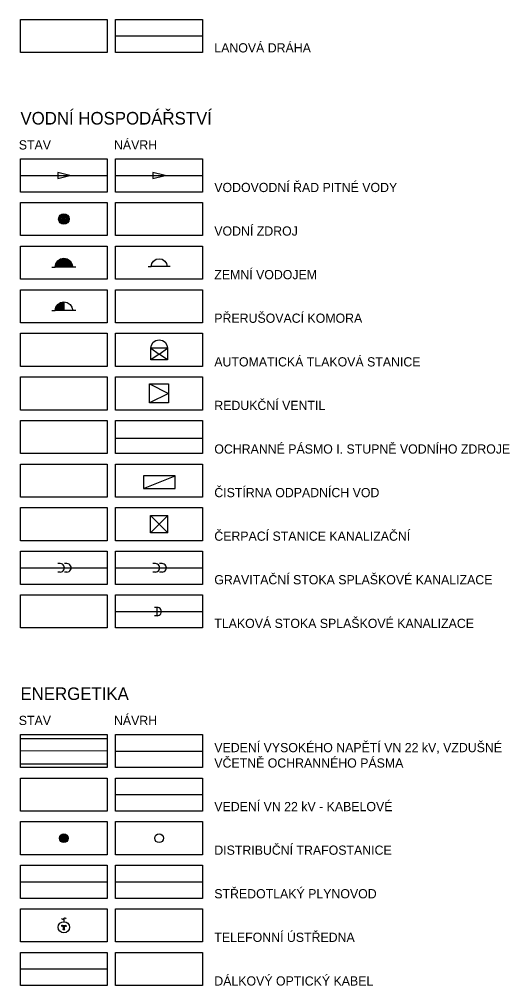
# Model space of a CAD drawing. Extents: x -439236 to -436121, y -1128919 to -1121098.
# Drawn here: x -439126 to -438541, y -1128630 to -1127477 of the extents above; entities that cross this region are included whole.
import ezdxf

# ---------------------------------------------------------------- set-up
doc = ezdxf.new("R2010")
doc.units = 0
for name, color, linetype in [('12210022_lanová dráha_Návrh', 7, 'Continuous'), ('13861012_venkovní vedení elektrické sítě VN 1-35 kV_Stav', 7, 'Continuous'), ('14250012_plynovod STL_Stav', 7, 'Continuous'), ('14801013_OP vedení elektrické sítě_Stav', 7, 'Continuous'), ('Trafostanice', 7, 'Continuous'), ('Vrstva 1', 7, 'Continuous'), ('Vrstva 10', 7, 'Continuous'), ('Vrstva 11', 7, 'Continuous'), ('Vrstva 12', 7, 'Continuous'), ('Vrstva 13', 7, 'Continuous'), ('Vrstva 14', 7, 'Continuous'), ('Vrstva 19', 7, 'Continuous'), ('Vrstva 27', 7, 'Continuous'), ('Vrstva 33', 7, 'Continuous'), ('Vrstva 34', 7, 'Continuous'), ('Vrstva 36', 7, 'Continuous'), ('Vrstva 39', 7, 'Continuous'), ('Vrstva 57', 7, 'Continuous'), ('Vrstva 58', 7, 'Continuous'), ('Vrstva 9', 7, 'Continuous')]:
    doc.layers.add(name, color=color, linetype=linetype)

msp = doc.modelspace()

# ---------------------------------------------------------------- linework, layer by layer
at = {"layer": '12210022_lanová dráha_Návrh'}
msp.add_line((-439011.8, -1127496.6), (-438907.2, -1127496.6), dxfattribs=at)
at = {"layer": '13861012_venkovní vedení elektrické sítě VN 1-35 kV_Stav'}
msp.add_line((-439011.3, -1128350), (-438907.7, -1128350), dxfattribs=at)
msp.add_lwpolyline([(-439021.3, -1128349.9), (-439124.9, -1128350.1)], dxfattribs=at)
at = {"layer": '14250012_plynovod STL_Stav'}
for p, q in [((-439124.9, -1128506.1), (-439021.3, -1128506.1)), ((-439011.3, -1128506.1), (-438907.7, -1128506.1))]:
    msp.add_line(p, q, dxfattribs=at)
at = {"layer": '14801013_OP vedení elektrické sítě_Stav'}
for p, q in [((-439124.9, -1128334.9), (-439021.3, -1128334.9)), ((-439021.3, -1128365.5), (-439124.9, -1128365.5))]:
    msp.add_line(p, q, dxfattribs=at)
at = {"layer": 'Trafostanice'}
for radius in [5.25, 4.55, 3.85, 3.15, 2.45, 1.75, 1.05, 0.35]:
    msp.add_circle((-439073.1, -1128454.1), radius, dxfattribs=at)
at = {"layer": 'Vrstva 1'}
for points in [[(-439124.9, -1127476.9), (-439021.3, -1127476.9), (-439021.3, -1127476.9), (-439021.3, -1127516.4), (-439124.9, -1127516.4)], [(-439011.3, -1127476.9), (-438907.7, -1127476.9), (-438907.7, -1127516.4), (-439011.3, -1127516.4)], [(-439124.9, -1127643.5), (-439021.3, -1127643.5), (-439021.3, -1127643.5), (-439021.3, -1127683), (-439124.9, -1127683)], [(-439011.3, -1127643.5), (-438907.7, -1127643.5), (-438907.7, -1127643.5), (-438907.7, -1127683), (-439011.3, -1127683)], [(-439124.9, -1127695.5), (-439021.3, -1127695.5), (-439021.3, -1127695.5), (-439021.3, -1127735), (-439124.9, -1127735)], [(-439011.3, -1127695.5), (-438907.7, -1127695.5), (-438907.7, -1127735), (-439011.3, -1127735)], [(-439124.9, -1127747.5), (-439021.3, -1127747.5), (-439021.3, -1127747.5), (-439021.3, -1127787), (-439124.9, -1127787)], [(-439011.3, -1127747.5), (-438907.7, -1127747.5), (-438907.7, -1127787), (-439011.3, -1127787)], [(-439124.9, -1127799.5), (-439021.3, -1127799.5), (-439021.3, -1127799.5), (-439021.3, -1127839), (-439124.9, -1127839)], [(-439011.3, -1127799.5), (-438907.7, -1127799.5), (-438907.7, -1127839), (-439011.3, -1127839)], [(-439124.9, -1127851.5), (-439021.3, -1127851.5), (-439021.3, -1127851.5), (-439021.3, -1127891.1), (-439124.9, -1127891.1)], [(-439011.3, -1127851.5), (-438907.7, -1127851.5), (-438907.7, -1127891.1), (-439011.3, -1127891.1)], [(-439124.9, -1127903.6), (-439021.3, -1127903.6), (-439021.3, -1127903.6), (-439021.3, -1127943.1), (-439124.9, -1127943.1)], [(-439011.3, -1127903.6), (-438907.7, -1127903.6), (-438907.7, -1127943.1), (-439011.3, -1127943.1)], [(-439124.9, -1127955.6), (-439021.3, -1127955.6), (-439021.3, -1127955.6), (-439021.3, -1127995.1), (-439124.9, -1127995.1)], [(-439011.3, -1127955.6), (-438907.7, -1127955.6), (-438907.7, -1127995.1), (-439011.3, -1127995.1)], [(-439124.9, -1128007.6), (-439021.3, -1128007.6), (-439021.3, -1128007.6), (-439021.3, -1128047.1), (-439124.9, -1128047.1)], [(-439011.3, -1128007.6), (-438907.7, -1128007.6), (-438907.7, -1128047.1), (-439011.3, -1128047.1)], [(-439124.9, -1128059.6), (-439021.3, -1128059.6), (-439021.3, -1128059.6), (-439021.3, -1128099.1), (-439124.9, -1128099.1)], [(-439011.3, -1128059.6), (-438907.7, -1128059.6), (-438907.7, -1128099.1), (-439011.3, -1128099.1)], [(-439124.9, -1128111.6), (-439021.3, -1128111.6), (-439021.3, -1128111.6), (-439021.3, -1128151.1), (-439124.9, -1128151.1)], [(-439011.3, -1128111.6), (-438907.7, -1128111.6), (-438907.7, -1128151.1), (-439011.3, -1128151.1)], [(-439124.9, -1128163.7), (-439021.3, -1128163.7), (-439021.3, -1128163.7), (-439021.3, -1128203.2), (-439124.9, -1128203.2)], [(-439011.3, -1128163.7), (-438907.7, -1128163.7), (-438907.7, -1128203.2), (-439011.3, -1128203.2)], [(-439124.9, -1128330.3), (-439021.3, -1128330.3), (-439021.3, -1128330.3), (-439021.3, -1128369.8), (-439124.9, -1128369.8)], [(-439011.3, -1128330.3), (-438907.7, -1128330.3), (-438907.7, -1128330.3), (-438907.7, -1128369.8), (-439011.3, -1128369.8)], [(-439124.9, -1128382.3), (-439021.3, -1128382.3), (-439021.3, -1128382.3), (-439021.3, -1128421.8), (-439124.9, -1128421.8)], [(-439011.3, -1128382.3), (-438907.7, -1128382.3), (-438907.7, -1128421.8), (-439011.3, -1128421.8)], [(-439124.9, -1128434.3), (-439021.3, -1128434.3), (-439021.3, -1128434.3), (-439021.3, -1128473.8), (-439124.9, -1128473.8)], [(-439011.3, -1128434.3), (-438907.7, -1128434.3), (-438907.7, -1128473.8), (-439011.3, -1128473.8)], [(-439124.9, -1128486.3), (-439021.3, -1128486.3), (-439021.3, -1128486.3), (-439021.3, -1128525.8), (-439124.9, -1128525.8)], [(-439011.3, -1128486.3), (-438907.7, -1128486.3), (-438907.7, -1128525.8), (-439011.3, -1128525.8)], [(-439124.9, -1128538.3), (-439021.3, -1128538.3), (-439021.3, -1128538.3), (-439021.3, -1128577.8), (-439124.9, -1128577.8)], [(-439011.3, -1128538.3), (-438907.7, -1128538.3), (-438907.7, -1128577.8), (-439011.3, -1128577.8)], [(-439124.9, -1128590.4), (-439021.3, -1128590.4), (-439021.3, -1128590.4), (-439021.3, -1128629.9), (-439124.9, -1128629.9)], [(-439011.3, -1128590.4), (-438907.7, -1128590.4), (-438907.7, -1128629.9), (-439011.3, -1128629.9)]]:
    msp.add_lwpolyline(points, close=True, dxfattribs=at)
at = {"layer": 'Vrstva 10'}
for p, q in [((-438972.6, -1127772), (-438969, -1127772)), ((-438946.3, -1127772), (-438949.9, -1127772)), ((-438949.5, -1127883.3), (-438969.5, -1127883.3))]:
    msp.add_line(p, q, dxfattribs=at)
for points in [[(-438969, -1127772), (-438968.3, -1127768.4), (-438966.2, -1127765.3), (-438963.1, -1127763.2), (-438959.5, -1127762.5), (-438955.8, -1127763.2), (-438952.7, -1127765.3), (-438950.7, -1127768.4), (-438949.9, -1127772)], [(-438969.5, -1127869.3), (-438968.7, -1127865.5), (-438966.5, -1127862.2), (-438963.3, -1127860.1), (-438959.5, -1127859.3), (-438955.6, -1127860.1), (-438952.4, -1127862.2), (-438950.2, -1127865.5), (-438949.5, -1127869.3)], [(-438969.5, -1127869.3), (-438959.5, -1127876.3), (-438969.5, -1127883.3)], [(-438949.5, -1127869.3), (-438949.5, -1127883.3), (-438959.5, -1127876.3)], [(-438970.8, -1127912), (-438948.2, -1127923.3), (-438970.8, -1127934.6)]]:
    msp.add_lwpolyline(points, close=True, dxfattribs=at)
msp.add_lwpolyline([(-438970.8, -1127912), (-438948.2, -1127912), (-438948.2, -1127923.3), (-438948.2, -1127934.6), (-438970.8, -1127934.6)], dxfattribs=at)
at = {"layer": 'Vrstva 11'}
for p, q in [((-439124.9, -1127663.2), (-439021.3, -1127663.2)), ((-439087.5, -1127824.5), (-439083.5, -1127824.5)), ((-439058.7, -1127824.5), (-439062.6, -1127824.5))]:
    msp.add_line(p, q, dxfattribs=at)
for points in [[(-439083.5, -1127824.5), (-439082.7, -1127820.5), (-439080.5, -1127817.1), (-439077.1, -1127814.9), (-439073.1, -1127814.1), (-439073.1, -1127824.5)], [(-439082.3, -1127823.5), (-439081.8, -1127820.9), (-439079.8, -1127817.8), (-439076.7, -1127815.8), (-439074.1, -1127815.3), (-439074.1, -1127823.5)], [(-439081.1, -1127822.5), (-439080.9, -1127821.3), (-439079, -1127818.6), (-439076.3, -1127816.7), (-439075.1, -1127816.5), (-439075.1, -1127822.5)], [(-439078.3, -1127819.3), (-439076.1, -1127817.8), (-439076.1, -1127821.5), (-439079.8, -1127821.5)], [(-439077.9, -1127820.5), (-439077.6, -1127820), (-439077.1, -1127819.7), (-439077.1, -1127820.5)]]:
    msp.add_lwpolyline(points, close=True, dxfattribs=at)
msp.add_lwpolyline([(-439073.1, -1127814.1), (-439069.1, -1127814.9), (-439065.7, -1127817.1), (-439063.4, -1127820.5), (-439062.6, -1127824.5), (-439073.1, -1127824.5)], dxfattribs=at)
at = {"layer": 'Vrstva 12'}
msp.add_lwpolyline([(-439080.4, -1127659.6), (-439080.4, -1127666.9), (-439065.8, -1127663.2)], close=True, dxfattribs=at)
at = {"layer": 'Vrstva 13'}
for p, q in [((-439011.3, -1127663.3), (-438907.7, -1127663.1)), ((-439011.3, -1128402), (-438907.7, -1128402))]:
    msp.add_line(p, q, dxfattribs=at)
at = {"layer": 'Vrstva 14'}
msp.add_lwpolyline([(-438966.8, -1127659.6), (-438966.8, -1127666.9), (-438952.2, -1127663.2)], close=True, dxfattribs=at)
at = {"layer": 'Vrstva 19'}
msp.add_circle((-438959.5, -1128454.1), 5.25, dxfattribs=at)
at = {"layer": 'Vrstva 27'}
msp.add_line((-439011.3, -1127976.7), (-438907.7, -1127976.7), dxfattribs=at)
at = {"layer": 'Vrstva 33'}
for p, q in [((-438969.7, -1128069.1), (-438949.2, -1128069.1)), ((-438969.7, -1128069.1), (-438949.2, -1128089.7)), ((-438969.7, -1128089.7), (-438969.7, -1128069.1)), ((-438949.2, -1128069.1), (-438959.5, -1128079.4)), ((-438949.2, -1128089.7), (-438949.2, -1128069.1)), ((-438959.5, -1128079.4), (-438969.7, -1128089.7)), ((-438949.2, -1128089.7), (-438969.7, -1128089.7))]:
    msp.add_line(p, q, dxfattribs=at)
msp.add_lwpolyline([(-438978.1, -1128036.7), (-438940.3, -1128036.7), (-438940.3, -1128021.5), (-438978.1, -1128021.5)], close=True, dxfattribs=at)
msp.add_lwpolyline([(-438978.1, -1128036.7), (-438940.3, -1128021.5)], dxfattribs=at)
at = {"layer": 'Vrstva 34'}
msp.add_line((-439124.9, -1128131.4), (-439021.3, -1128131.4), dxfattribs=at)
at = {"layer": 'Vrstva 36'}
for p, q in [((-439011.3, -1128131.4), (-438907.7, -1128131.4)), ((-439011.3, -1128183.4), (-438907.7, -1128183.4))]:
    msp.add_line(p, q, dxfattribs=at)
at = {"layer": 'Vrstva 39'}
for p, q in [((-439077.4, -1128126.4), (-439080.4, -1128126.4)), ((-439069.4, -1128126.4), (-439072.4, -1128126.4)), ((-438963.8, -1128126.4), (-438966.8, -1128126.4)), ((-438955.8, -1128126.4), (-438958.8, -1128126.4)), ((-439077.4, -1128136.4), (-439080.4, -1128136.4)), ((-439069.4, -1128136.4), (-439072.4, -1128136.4)), ((-438963.8, -1128136.4), (-438966.8, -1128136.4)), ((-438955.8, -1128136.4), (-438958.8, -1128136.4)), ((-438961.9, -1128178.6), (-438964.9, -1128178.6)), ((-438961.9, -1128188.6), (-438961.9, -1128178.6)), ((-438961.9, -1128188.6), (-438964.9, -1128188.6))]:
    msp.add_line(p, q, dxfattribs=at)
for centre, start in [((-439077.4, -1128131.4), 270), ((-439069.4, -1128131.4), 270), ((-438963.8, -1128131.4), 270), ((-438955.8, -1128131.4), 270), ((-438961.9, -1128183.6), 270.0004)]:
    msp.add_arc(centre, 5, start, 90.0011, dxfattribs=at)
at = {"layer": 'Vrstva 57'}
for p, q in [((-439073.1, -1128549.9), (-439073.1, -1128553.6)), ((-439075.2, -1128559.2), (-439075.5, -1128558.9)), ((-439074.8, -1128558.8), (-439075.4, -1128558.2)), ((-439074.5, -1128558.5), (-439074.8, -1128558.1)), ((-439073.8, -1128558.5), (-439074.1, -1128558.1)), ((-439073.8, -1128563.4), (-439074, -1128563.1)), ((-439073.1, -1128563.4), (-439073.7, -1128562.8)), ((-439072.6, -1128558.9), (-439073.4, -1128558.1)), ((-439072.6, -1128559.6), (-439073.4, -1128558.9)), ((-439072.6, -1128560.3), (-439073.4, -1128559.6)), ((-439072.6, -1128561), (-439073.4, -1128560.3)), ((-439072.6, -1128561.7), (-439073.4, -1128561)), ((-439072.6, -1128562.4), (-439073.4, -1128561.7)), ((-439072.4, -1128563.4), (-439073.4, -1128562.4)), ((-439072.4, -1128558.5), (-439072.7, -1128558.1)), ((-439071.6, -1128558.5), (-439072, -1128558.1)), ((-439070.5, -1128558.9), (-439071.3, -1128558.1)), ((-439070.6, -1128558.1), (-439070.7, -1128558))]:
    msp.add_line(p, q, dxfattribs=at)
msp.add_lwpolyline([(-439076, -1128549.4), (-439075.5, -1128550.1), (-439074.8, -1128550.6), (-439074.4, -1128550.7), (-439074, -1128550.6), (-439073.5, -1128550.3), (-439073.1, -1128549.9), (-439072.7, -1128549.4), (-439072.1, -1128549.1), (-439071.7, -1128549.1), (-439071.3, -1128549.2), (-439070.7, -1128549.7), (-439070.2, -1128550.3)], dxfattribs=at)
msp.add_lwpolyline([(-439070.6, -1128558), (-439070.4, -1128559.4), (-439070.6, -1128559.4), (-439071.5, -1128558.5), (-439072.6, -1128558.5), (-439072.6, -1128562.6), (-439071.9, -1128563.2), (-439071.9, -1128563.4), (-439074.1, -1128563.4), (-439074.1, -1128563.2), (-439073.4, -1128562.6), (-439073.4, -1128558.5), (-439074.5, -1128558.5), (-439075.4, -1128559.4), (-439075.6, -1128559.4), (-439075.4, -1128558), (-439075.2, -1128558), (-439074.9, -1128558.1), (-439071.1, -1128558.1), (-439070.8, -1128558)], close=True, dxfattribs=at)
msp.add_circle((-439073.1, -1128560.4), 6.75, dxfattribs=at)
at = {"layer": 'Vrstva 58'}
msp.add_line((-439124.9, -1128610.1), (-439021.3, -1128610.1), dxfattribs=at)
at = {"layer": 'Vrstva 9'}
for p, q in [((-439087.5, -1127772.5), (-439083.5, -1127772.5)), ((-439058.7, -1127772.5), (-439062.6, -1127772.5))]:
    msp.add_line(p, q, dxfattribs=at)
for points in [[(-439083.5, -1127772.5), (-439082.7, -1127768.5), (-439080.5, -1127765.1), (-439077.1, -1127762.8), (-439073.1, -1127762), (-439069.1, -1127762.8), (-439065.7, -1127765.1), (-439063.4, -1127768.5), (-439062.6, -1127772.5)], [(-439082.3, -1127771.5), (-439081.8, -1127768.9), (-439079.8, -1127765.8), (-439076.7, -1127763.8), (-439073.1, -1127763.1), (-439069.5, -1127763.8), (-439066.4, -1127765.8), (-439064.4, -1127768.9), (-439063.9, -1127771.5)], [(-439081.1, -1127770.5), (-439080.9, -1127769.3), (-439079, -1127766.5), (-439076.3, -1127764.7), (-439073.1, -1127764.1), (-439069.9, -1127764.7), (-439067.1, -1127766.5), (-439065.3, -1127769.3), (-439065.1, -1127770.5)], [(-439079.8, -1127769.5), (-439078.3, -1127767.3), (-439075.9, -1127765.7), (-439073.1, -1127765.1), (-439070.3, -1127765.7), (-439067.9, -1127767.3), (-439066.4, -1127769.5)], [(-439077.9, -1127768.5), (-439077.6, -1127768), (-439075.5, -1127766.6), (-439073.1, -1127766.1), (-439070.6, -1127766.6), (-439068.6, -1127768), (-439068.2, -1127768.5)], [(-439074.9, -1127767.5), (-439073.1, -1127767.1), (-439071.3, -1127767.5)]]:
    msp.add_lwpolyline(points, close=True, dxfattribs=at)
for radius in [6.3, 5.3, 4.3, 3.3, 2.3, 1.3, 0.3]:
    msp.add_circle((-439073.1, -1127715.2), radius, dxfattribs=at)

# ---------------------------------------------------------------- texts
at = {"layer": 'Vrstva 1'}
for s, height, p in [('LANOVÁ DRÁHA', 11, (-438893.6, -1127516.4)), ('VODNÍ HOSPODÁŘSTVÍ', 15, (-439124.9, -1127602.4)), ('NÁVRH', 11, (-439013.3, -1127632.2)), ('STAV', 11, (-439126.9, -1127632.2)), ('VODOVODNÍ ŘAD PITNÉ VODY', 11, (-438893.6, -1127683)), ('VODNÍ ZDROJ', 11, (-438893.6, -1127735)), ('ZEMNÍ VODOJEM', 11, (-438893.6, -1127787)), ('PŘERUŠOVACÍ KOMORA', 11, (-438893.6, -1127839)), ('AUTOMATICKÁ TLAKOVÁ STANICE', 11, (-438893.6, -1127891.1)), ('REDUKČNÍ VENTIL', 11, (-438893.6, -1127943.1)), ('OCHRANNÉ PÁSMO I. STUPNĚ VODNÍHO ZDROJE', 11, (-438893.6, -1127995.1)), ('ČISTÍRNA ODPADNÍCH VOD', 11, (-438893.6, -1128047.1)), ('ČERPACÍ STANICE KANALIZAČNÍ', 11, (-438893.6, -1128099.1)), ('GRAVITAČNÍ STOKA SPLAŠKOVÉ KANALIZACE', 11, (-438893.6, -1128151.1)), ('TLAKOVÁ STOKA SPLAŠKOVÉ KANALIZACE', 11, (-438893.6, -1128203.2)), ('ENERGETIKA', 15, (-439124.9, -1128289.1)), ('STAV', 11, (-439126.9, -1128319)), ('NÁVRH', 11, (-439013.3, -1128319)), ('VEDENÍ VYSOKÉHO NAPĚTÍ VN 22 kV, VZDUŠNÉ', 11, (-438893.6, -1128351.4)), ('VČETNĚ OCHRANNÉHO PÁSMA', 11, (-438893.6, -1128369.8)), ('VEDENÍ VN 22 kV - KABELOVÉ', 11, (-438893.6, -1128421.8)), ('DISTRIBUČNÍ TRAFOSTANICE', 11, (-438893.6, -1128473.8)), ('STŘEDOTLAKÝ PLYNOVOD', 11, (-438893.6, -1128525.8)), ('TELEFONNÍ ÚSTŘEDNA', 11, (-438893.6, -1128577.8)), ('DÁLKOVÝ OPTICKÝ KABEL', 11, (-438893.6, -1128629.9))]:
    msp.add_text(s, height=height, dxfattribs=at).set_placement(p)

doc.saveas('drawing.dxf')
